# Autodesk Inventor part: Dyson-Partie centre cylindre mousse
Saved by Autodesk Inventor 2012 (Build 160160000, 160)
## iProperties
Created: 2012-11
Part Number: Dyson-Partie centre cylindre mousse
Material: Default
Document SubType Name: Modeling
Designer: Administrateur
Density: 1 g/cm^3
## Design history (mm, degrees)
node "Dyson-Partie centre cylindre mousse1"
node "Dyson-Partie centre cylindre mousse"
node "Base1"
